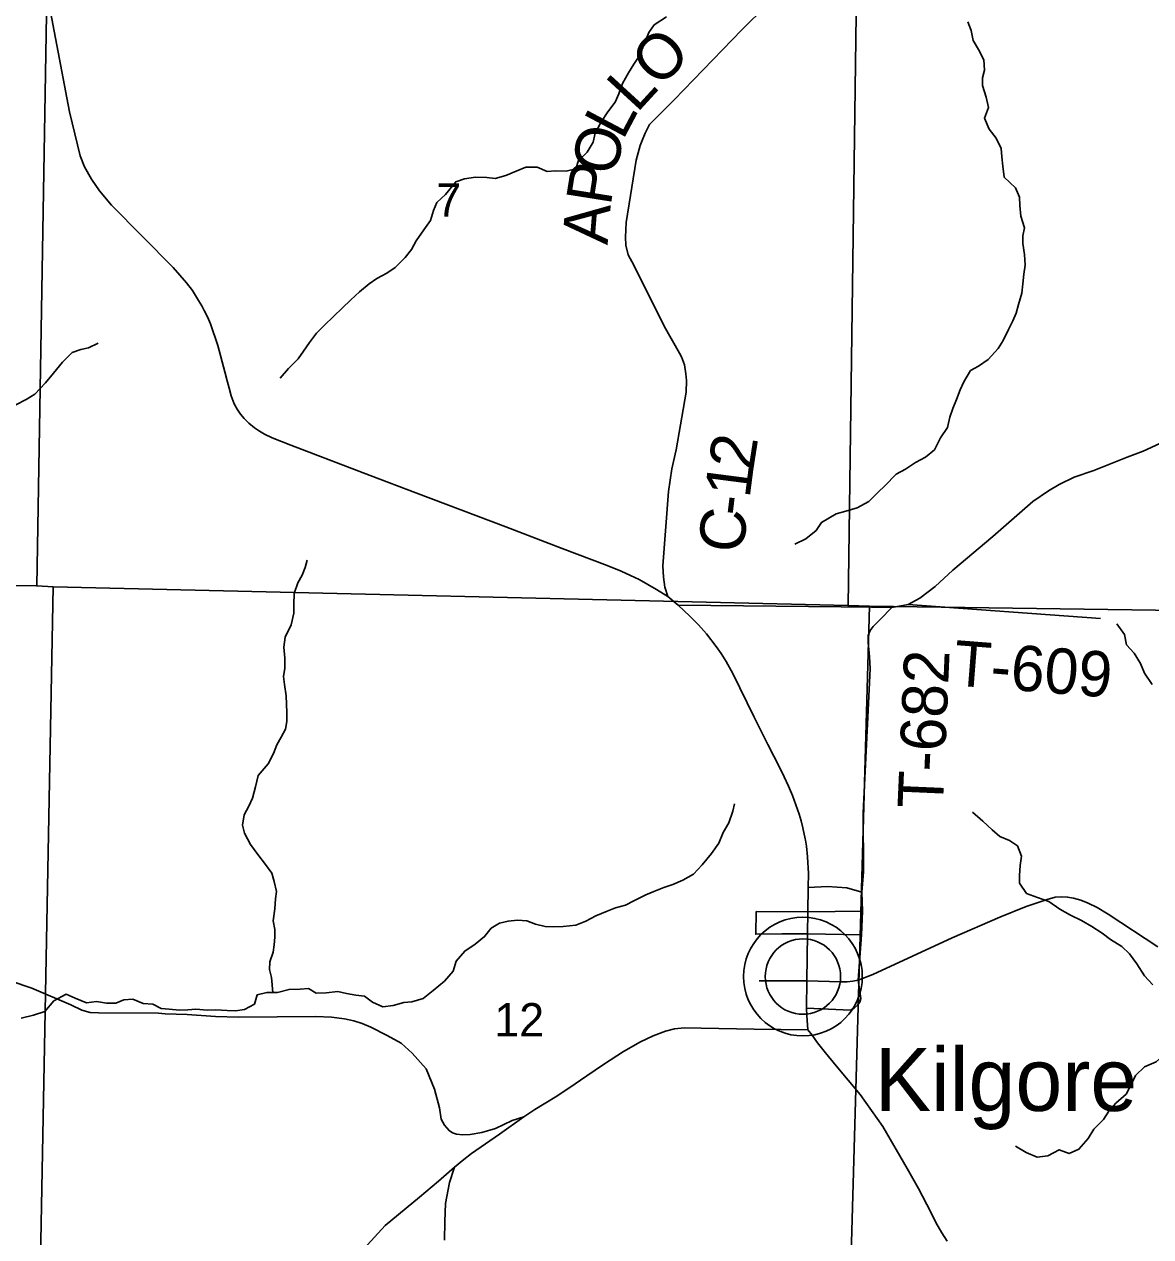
# Model space of a CAD drawing. Extents: x -3.6 to 34, y 0 to 32.8.
# Drawn here: x -1.822 to -0.41, y 28.286 to 29.806 of the extents above; entities that cross this region are included whole.
import ezdxf

# ---------------------------------------------------------------- set-up
doc = ezdxf.new("R2010")
doc.units = 0
for name, color, linetype in [('GM_X_Corporation', 7, 'Continuous'), ('GM_X_County_Road', 7, 'Continuous'), ('GM_X_County_Road_Text', 7, 'Continuous'), ('GM_X_Minor_River', 7, 'Continuous'), ('GM_X_Section_Text', 7, 'Continuous'), ('GM_X_State_Route', 7, 'Continuous'), ('GM_X_Township_Road', 7, 'Continuous'), ('GM_X_Township_Road_Text', 7, 'Continuous'), ('GM_X_Unincorporated', 7, 'Continuous'), ('GM_X_Unincorporated_Location', 7, 'Continuous'), ('GM_X_Unincorporated_Text', 7, 'Continuous')]:
    doc.layers.add(name, color=color, linetype=linetype)

msp = doc.modelspace()

# ---------------------------------------------------------------- linework, layer by layer
at = {"layer": 'GM_X_Corporation'}
for points in [[(-1.7886, 30.1145), (-1.8059, 29.1018), (-2.8121, 29.1143), (-2.8032, 30.1329)], [(-0.7755, 30.0957), (-0.7893, 29.0771), (-1.7854, 29.1006), (-1.8059, 29.1018), (-1.7886, 30.1145)], [(-0.7755, 30.0957), (0.2459, 30.0789), (0.244, 29.9924), (0.223, 29.0627), (-0.7627, 29.0764), (-0.7893, 29.0771)], [(-2.8121, 29.1143), (-1.8059, 29.1018), (-1.7854, 29.1006), (-1.8056, 28.0368), (-2.8264, 28.0607)], [(-1.7854, 29.1006), (-0.7893, 29.0771), (-0.7627, 29.0764), (-0.7925, 28.0131), (-1.8056, 28.0368)], [(-0.7627, 29.0764), (0.223, 29.0627), (0.2209, 28.9831), (0.2524, 28.9828), (0.2336, 27.9902), (-0.7925, 28.0131)]]:
    msp.add_lwpolyline(points, close=True, dxfattribs=at)
at = {"layer": 'GM_X_County_Road'}
for points in [[(-1.0152, 29.0884), (-1.0189, 29.1001), (-1.0207, 29.1126), (-1.0216, 29.1271), (-1.0143, 29.2203), (-1.01, 29.2486), (-1.0049, 29.2725), (-0.9923, 29.3448), (-0.9918, 29.3592), (-0.9927, 29.3675), (-0.9944, 29.379), (-0.9979, 29.389), (-1.0004, 29.3936), (-1.0199, 29.4275), (-1.058, 29.5039), (-1.0649, 29.5167), (-1.068, 29.5289), (-1.0684, 29.539), (-1.0675, 29.5572), (-1.0547, 29.6353), (-1.0497, 29.6536), (-1.0473, 29.6601), (-1.0435, 29.6693), (-1.0381, 29.6799), (-1.0074, 29.7109), (-0.9225, 29.7987), (-0.8913, 29.8296)], [(-0.3986, 29.2802), (-0.4194, 29.2707), (-0.4398, 29.263), (-0.4816, 29.2465), (-0.5061, 29.238), (-0.5248, 29.2291), (-0.5383, 29.2211), (-0.558, 29.2075), (-0.6078, 29.1636), (-0.6582, 29.1216), (-0.6802, 29.1011), (-0.6995, 29.0863), (-0.7139, 29.0786), (-0.7344, 29.0749), (-0.7599, 29.0751), (-0.7981, 29.0758), (-1.0024, 29.0776)], [(-1.8378, 28.6067), (-1.8123, 28.5976), (-1.7632, 28.5767), (-1.7493, 28.5703), (-1.7388, 28.5674), (-1.7286, 28.5667), (-1.6532, 28.5663), (-1.6449, 28.5656), (-1.6176, 28.5646), (-1.5819, 28.5622), (-1.5531, 28.5614), (-1.4564, 28.5624), (-1.4368, 28.5615), (-1.4204, 28.5594), (-1.4087, 28.5569), (-1.3981, 28.5535), (-1.3874, 28.5489), (-1.367, 28.5386), (-1.3493, 28.5287), (-1.3357, 28.5163), (-1.3181, 28.4965), (-1.3075, 28.471), (-1.3013, 28.448), (-1.2993, 28.4336), (-1.295, 28.426), (-1.2892, 28.4193), (-1.2849, 28.4164), (-1.28, 28.415), (-1.2721, 28.4139), (-1.263, 28.4143), (-1.2481, 28.4167), (-1.2311, 28.4218), (-1.2102, 28.4319), (-1.1957, 28.4367)], [(-1.2824, 28.3736), (-1.2889, 28.3544), (-1.2936, 28.3279), (-1.2948, 28.3054), (-1.2951, 28.2819)]]:
    msp.add_lwpolyline(points, dxfattribs=at)
at = {"layer": 'GM_X_Minor_River'}
for points in [[(-1.0169, 29.8148), (-1.0322, 29.8051), (-1.0392, 29.7955), (-1.0465, 29.7764), (-1.0512, 29.7657), (-1.0579, 29.7558), (-1.0645, 29.745), (-1.0718, 29.7313), (-1.0765, 29.7183), (-1.0813, 29.708), (-1.0905, 29.6961), (-1.099, 29.6827), (-1.1063, 29.6693), (-1.1088, 29.6579), (-1.1161, 29.6456), (-1.1273, 29.6348), (-1.1305, 29.6245), (-1.1426, 29.6216), (-1.1559, 29.6222), (-1.1664, 29.6212), (-1.179, 29.6267), (-1.193, 29.6265), (-1.2051, 29.6217), (-1.2182, 29.6162), (-1.2314, 29.6126), (-1.242, 29.6135), (-1.256, 29.614), (-1.27, 29.6119), (-1.2809, 29.6083), (-1.2939, 29.5925), (-1.3047, 29.5825), (-1.3087, 29.5722), (-1.3126, 29.5596), (-1.3208, 29.5481), (-1.3304, 29.5343), (-1.3362, 29.5236), (-1.3444, 29.5136), (-1.357, 29.5009), (-1.3671, 29.4939), (-1.3799, 29.4872), (-1.3896, 29.4806), (-1.4016, 29.4702), (-1.4124, 29.4605), (-1.4232, 29.4501), (-1.4336, 29.44), (-1.4459, 29.4281), (-1.4552, 29.4184), (-1.4641, 29.4069), (-1.4718, 29.3962), (-1.4785, 29.3866), (-1.4907, 29.3743), (-1.5008, 29.362)], [(-0.6391, 29.8086), (-0.6352, 29.7977), (-0.6327, 29.7852), (-0.6261, 29.7739), (-0.6191, 29.7611), (-0.6185, 29.7482), (-0.621, 29.7387), (-0.6209, 29.7289), (-0.6165, 29.7145), (-0.6133, 29.7013), (-0.6184, 29.6879), (-0.6125, 29.6744), (-0.6036, 29.6631), (-0.5977, 29.6499), (-0.5968, 29.6397), (-0.5955, 29.628), (-0.5938, 29.614), (-0.5796, 29.6005), (-0.5745, 29.5892), (-0.5743, 29.5786), (-0.573, 29.5654), (-0.5682, 29.5506), (-0.5703, 29.5404), (-0.5702, 29.5309), (-0.5681, 29.5173), (-0.5675, 29.504), (-0.5692, 29.4926), (-0.5702, 29.4804), (-0.5715, 29.4687), (-0.5758, 29.4546), (-0.5787, 29.4435), (-0.5831, 29.434), (-0.5882, 29.4233), (-0.5952, 29.4095), (-0.6011, 29.3992), (-0.6137, 29.3857), (-0.6261, 29.3772), (-0.6359, 29.3717), (-0.6443, 29.3575), (-0.6487, 29.3476), (-0.6535, 29.3354), (-0.6582, 29.324), (-0.6618, 29.3133), (-0.6647, 29.3003), (-0.6735, 29.2873), (-0.6809, 29.2724), (-0.6925, 29.2631), (-0.7049, 29.2565), (-0.7172, 29.2483), (-0.7292, 29.2417), (-0.7431, 29.2271)], [(-1.8322, 29.3286), (-1.8194, 29.3353), (-1.8085, 29.3423), (-1.7948, 29.3565), (-1.7851, 29.3685), (-1.7736, 29.3823), (-1.7614, 29.3943), (-1.7508, 29.3982), (-1.741, 29.4003), (-1.729, 29.4062)], [(-0.7431, 29.2271), (-0.7515, 29.2194), (-0.7634, 29.2078), (-0.778, 29.1996), (-0.7923, 29.1955), (-0.8044, 29.1923), (-0.8227, 29.1814), (-0.8294, 29.1714), (-0.8424, 29.161), (-0.8559, 29.1543)], [(-1.5102, 28.5923), (-1.512, 28.6112), (-1.5145, 28.6211), (-1.5139, 28.6309), (-1.5099, 28.6427), (-1.5086, 28.6522), (-1.5076, 28.6617), (-1.5078, 28.6712), (-1.5095, 28.6822), (-1.5075, 28.697), (-1.5069, 28.7095), (-1.5056, 28.719), (-1.5084, 28.7315), (-1.5113, 28.742), (-1.5194, 28.7529), (-1.5291, 28.7652), (-1.538, 28.7776), (-1.5458, 28.7922), (-1.5483, 28.8021), (-1.5462, 28.815), (-1.54, 28.8257), (-1.5356, 28.836), (-1.5317, 28.8501), (-1.5285, 28.8642), (-1.5159, 28.8788), (-1.5093, 28.8918), (-1.505, 28.9029), (-1.4998, 28.9124), (-1.4943, 28.9224), (-1.4926, 28.9319), (-1.4924, 28.9433), (-1.493, 28.9535), (-1.4935, 28.9641), (-1.4957, 28.9784), (-1.4966, 28.9883), (-1.4949, 28.9986), (-1.4951, 29.0111), (-1.4965, 29.0251), (-1.4948, 29.0376), (-1.4871, 29.0529), (-1.4839, 29.0677), (-1.4838, 29.0787), (-1.4832, 29.0924), (-1.4789, 29.1057), (-1.4734, 29.1153), (-1.4698, 29.1248), (-1.4669, 29.1343)], [(-0.4085, 28.9781), (-0.4178, 28.9927), (-0.4229, 29.0048), (-0.431, 29.0175), (-0.4403, 29.028), (-0.4431, 29.0409), (-0.4528, 29.0544)], [(-1.0091, 28.7275), (-0.9963, 28.733), (-0.9832, 28.7405), (-0.972, 28.7524), (-0.9605, 28.7666), (-0.9513, 28.7793), (-0.9459, 28.793), (-0.9389, 28.8049), (-0.9338, 28.8194), (-0.9317, 28.8289)], [(-0.4076, 28.6018), (-0.418, 28.6134), (-0.4277, 28.6284), (-0.4366, 28.6408), (-0.4462, 28.6501), (-0.4607, 28.6586), (-0.4711, 28.6668), (-0.4841, 28.675), (-0.4967, 28.6824), (-0.5108, 28.6894), (-0.5241, 28.6967), (-0.5379, 28.7064), (-0.552, 28.7115), (-0.5657, 28.7162), (-0.5746, 28.7293), (-0.5747, 28.7388), (-0.5738, 28.7514), (-0.5721, 28.7631), (-0.5772, 28.776), (-0.5871, 28.783), (-0.5993, 28.7878), (-0.6089, 28.7963), (-0.6204, 28.8072), (-0.6335, 28.8183)], [(-1.8253, 28.56), (-1.8099, 28.5641), (-1.796, 28.5685), (-1.7845, 28.5819), (-1.7691, 28.5902), (-1.7576, 28.5851), (-1.7435, 28.5792), (-1.7311, 28.581), (-1.7185, 28.5789), (-1.7068, 28.5791), (-1.6967, 28.5831), (-1.6857, 28.584), (-1.6724, 28.5786), (-1.6606, 28.5776), (-1.6499, 28.5721), (-1.6401, 28.5715), (-1.6272, 28.5702), (-1.6166, 28.5708), (-1.6064, 28.5713), (-1.592, 28.5701), (-1.5814, 28.5706), (-1.5674, 28.5697), (-1.5571, 28.5695), (-1.5458, 28.5709), (-1.533, 28.5779), (-1.5298, 28.5893), (-1.5178, 28.5922), (-1.5041, 28.5924), (-1.4898, 28.5961), (-1.4758, 28.5963), (-1.4656, 28.5973), (-1.4557, 28.5914), (-1.4432, 28.592), (-1.4288, 28.5937), (-1.4178, 28.5909), (-1.406, 28.5888), (-1.3954, 28.5878), (-1.3851, 28.5804), (-1.3721, 28.5742), (-1.3593, 28.576), (-1.3461, 28.58), (-1.3359, 28.5805), (-1.3216, 28.5846), (-1.3092, 28.595), (-1.2951, 28.6066), (-1.2843, 28.6189), (-1.2804, 28.6315), (-1.2696, 28.6442), (-1.2565, 28.6528), (-1.2449, 28.6624), (-1.2364, 28.6728), (-1.2263, 28.6794), (-1.2154, 28.6819), (-1.2036, 28.6829), (-1.1919, 28.6823), (-1.1812, 28.6779), (-1.1687, 28.6751), (-1.1588, 28.6745), (-1.1463, 28.6751), (-1.1305, 28.6769), (-1.1181, 28.6817), (-1.1053, 28.6883), (-1.0914, 28.6943), (-1.0809, 28.6986), (-1.0681, 28.7019), (-1.0576, 28.707), (-1.0426, 28.7148), (-1.0328, 28.7191), (-1.0204, 28.7239), (-1.0091, 28.7275)], [(-0.3547, 28.5599), (-0.3686, 28.5462), (-0.3756, 28.5363), (-0.383, 28.5267), (-0.3916, 28.5159), (-0.4035, 28.5055), (-0.4178, 28.4992), (-0.4294, 28.4884), (-0.4341, 28.4777), (-0.4408, 28.4651), (-0.4538, 28.4535), (-0.4627, 28.4435), (-0.4694, 28.4332), (-0.4813, 28.4209), (-0.4887, 28.4094), (-0.5002, 28.3959), (-0.5123, 28.3904), (-0.5248, 28.3952), (-0.5391, 28.3877), (-0.5523, 28.386), (-0.566, 28.3919), (-0.5794, 28.3996)]]:
    msp.add_lwpolyline(points, dxfattribs=at)
at = {"layer": 'GM_X_State_Route'}
for p, q in [((-0.8416, 28.5725), (-0.841, 28.6069)), ((-0.841, 28.5635), (-0.8416, 28.5725)), ((-0.8398, 28.5456), (-0.841, 28.5635))]:
    msp.add_line(p, q, dxfattribs=at)
for points in [[(-0.8428, 28.7831), (-0.8432, 28.785), (-0.8461, 28.7986), (-0.8482, 28.8075), (-0.8506, 28.816), (-0.8546, 28.8276), (-0.8588, 28.839), (-0.864, 28.8508), (-0.8696, 28.8625), (-0.8763, 28.8762), (-0.8823, 28.8886), (-0.8899, 28.9032), (-0.9069, 28.9372), (-0.9338, 28.9922), (-0.942, 29.007), (-0.9482, 29.017), (-0.9545, 29.0261), (-0.9667, 29.0416), (-0.9768, 29.053), (-0.9875, 29.064), (-1.0024, 29.0776), (-1.0152, 29.0884), (-1.0294, 29.0972), (-1.0401, 29.1035), (-1.0513, 29.1098), (-1.0621, 29.115), (-1.0737, 29.1202), (-1.0913, 29.1274), (-1.1477, 29.1487), (-1.218, 29.1757), (-1.3311, 29.2185), (-1.3881, 29.2404), (-1.4874, 29.2781), (-1.511, 29.2875), (-1.5206, 29.2922), (-1.5268, 29.2959), (-1.533, 29.3), (-1.5401, 29.3056), (-1.5462, 29.3117), (-1.5505, 29.3172), (-1.5548, 29.3232), (-1.5584, 29.3302), (-1.5623, 29.3402), (-1.565, 29.3496), (-1.5675, 29.3588), (-1.5703, 29.37), (-1.579, 29.4032), (-1.5881, 29.4302), (-1.5919, 29.439), (-1.5961, 29.4469), (-1.5989, 29.4528), (-1.6032, 29.4596), (-1.6107, 29.4722), (-1.6184, 29.4816), (-1.6348, 29.5009), (-1.7121, 29.5788), (-1.7275, 29.5969), (-1.7374, 29.6115), (-1.7459, 29.6271), (-1.7516, 29.6409), (-1.7649, 29.6958), (-1.7902, 29.83)], [(-0.841, 28.6069), (-0.8401, 28.6659), (-0.8399, 28.6933), (-0.8392, 28.7238), (-0.8391, 28.7416), (-0.84, 28.7622), (-0.8416, 28.7758), (-0.8428, 28.7831)], [(-0.841, 28.6069), (-0.7983, 28.6055), (-0.7903, 28.6058), (-0.7834, 28.6064), (-0.7769, 28.6077), (-0.7583, 28.6148), (-0.6589, 28.6609), (-0.5993, 28.6869), (-0.5663, 28.7), (-0.54, 28.7088), (-0.5297, 28.7119), (-0.5214, 28.7123), (-0.5143, 28.712), (-0.5068, 28.7104), (-0.4979, 28.708), (-0.4887, 28.7043), (-0.4772, 28.6989), (-0.4635, 28.6907), (-0.4014, 28.6497)], [(-1.4901, 28.1685), (-1.3693, 28.3004), (-1.3265, 28.336), (-1.3027, 28.356), (-1.2824, 28.3736), (-1.2708, 28.3831), (-1.261, 28.3907), (-1.226, 28.415), (-1.1957, 28.4367), (-1.182, 28.4456), (-1.1565, 28.4613), (-1.1394, 28.4724), (-1.1168, 28.4879), (-1.0957, 28.502), (-1.0709, 28.5182), (-1.0496, 28.5304), (-1.0334, 28.5382), (-1.0182, 28.5438), (-1.0067, 28.5466), (-0.9943, 28.5479), (-0.9736, 28.5478), (-0.9072, 28.5463), (-0.8398, 28.5456)], [(-0.6652, 28.2808), (-0.6719, 28.2911), (-0.6794, 28.3041), (-0.6857, 28.3169), (-0.7012, 28.3466), (-0.7153, 28.3717), (-0.7459, 28.4245), (-0.7743, 28.4647), (-0.8042, 28.5005), (-0.8177, 28.5169), (-0.826, 28.5272), (-0.8289, 28.5309), (-0.8314, 28.5345), (-0.8342, 28.5387), (-0.8398, 28.5456)]]:
    msp.add_lwpolyline(points, dxfattribs=at)
at = {"layer": 'GM_X_Township_Road'}
for p, q in [((-0.7139, 29.0786), (-0.4732, 29.0612)), ((-0.8399, 28.6933), (-0.7714, 28.6942)), ((-0.841, 28.6069), (-0.9008, 28.6071))]:
    msp.add_line(p, q, dxfattribs=at)
for points in [[(-0.7344, 29.0749), (-0.7487, 29.0602), (-0.7578, 29.0509), (-0.7616, 29.0461), (-0.7643, 29.0399), (-0.7642, 29.0305), (-0.7632, 29.022), (-0.7626, 29.0129), (-0.7616, 28.9982), (-0.7645, 28.9374), (-0.7685, 28.861), (-0.7703, 28.817), (-0.7699, 28.743), (-0.772, 28.7179)], [(-0.772, 28.7179), (-0.7908, 28.7237), (-0.8153, 28.725), (-0.8392, 28.7238)], [(-0.7769, 28.6077), (-0.7726, 28.6644), (-0.7714, 28.6942), (-0.772, 28.7179)], [(-0.8714, 28.6658), (-0.8724, 28.6658), (-0.905, 28.6653), (-0.9044, 28.6938), (-0.8399, 28.6933)], [(-0.7726, 28.6644), (-0.8401, 28.6659), (-0.8714, 28.6658)], [(-0.8416, 28.5725), (-0.7862, 28.5702), (-0.7812, 28.573), (-0.7774, 28.5765), (-0.7748, 28.5803), (-0.7735, 28.5848), (-0.7769, 28.6077)]]:
    msp.add_lwpolyline(points, dxfattribs=at)
at = {"layer": 'GM_X_Unincorporated'}
for radius in [0.0744, 0.0472]:
    msp.add_circle((-0.8459, 28.6123), radius, dxfattribs=at)
at = {"layer": 'GM_X_Unincorporated_Location'}
msp.add_line((-0.8459, 28.6123), (-0.8459, 28.6123), dxfattribs=at)

# ---------------------------------------------------------------- texts
at = {"layer": 'GM_X_County_Road_Text'}
for s, rotation, p in [('O', 45.5783, (-1.0256, 29.7247)), ('L', 47.4539, (-1.054, 29.6937)), ('L', 62.1143, (-1.0717, 29.6593)), ('O', 77.5233, (-1.0811, 29.6142)), ('P', 80.9681, (-1.0869, 29.5773)), ('A', 85.4637, (-1.0907, 29.5286)), ('2', 81.0968, (-0.9084, 29.2451)), ('1', 82.6265, (-0.9128, 29.2108)), ('-', 83.0827, (-0.9156, 29.1878)), ('C', 83.2047, (-0.9212, 29.1415))]:
    msp.add_text(s, height=0.0568, rotation=rotation, dxfattribs=at).set_placement(p)
at = {"layer": 'GM_X_Section_Text'}
for s, height, p in [('7', 0.0419, (-1.3054, 29.5645)), ('12', 0.04186, (-1.2325, 28.5372))]:
    msp.add_text(s, height=height, rotation=0, dxfattribs=at).set_placement(p)
at = {"layer": 'GM_X_Township_Road_Text'}
for s, rotation, p in [('T-609', 355.5152, (-0.6586, 28.9773)), ('T-682', 87.4983, (-0.6707, 28.822))]:
    msp.add_text(s, height=0.05682, rotation=rotation, dxfattribs=at).set_placement(p)
at = {"layer": 'GM_X_Unincorporated_Text'}
msp.add_text('Kilgore', height=0.07898, rotation=0, dxfattribs=at).set_placement((-0.7558, 28.4439))

doc.saveas('drawing.dxf')
